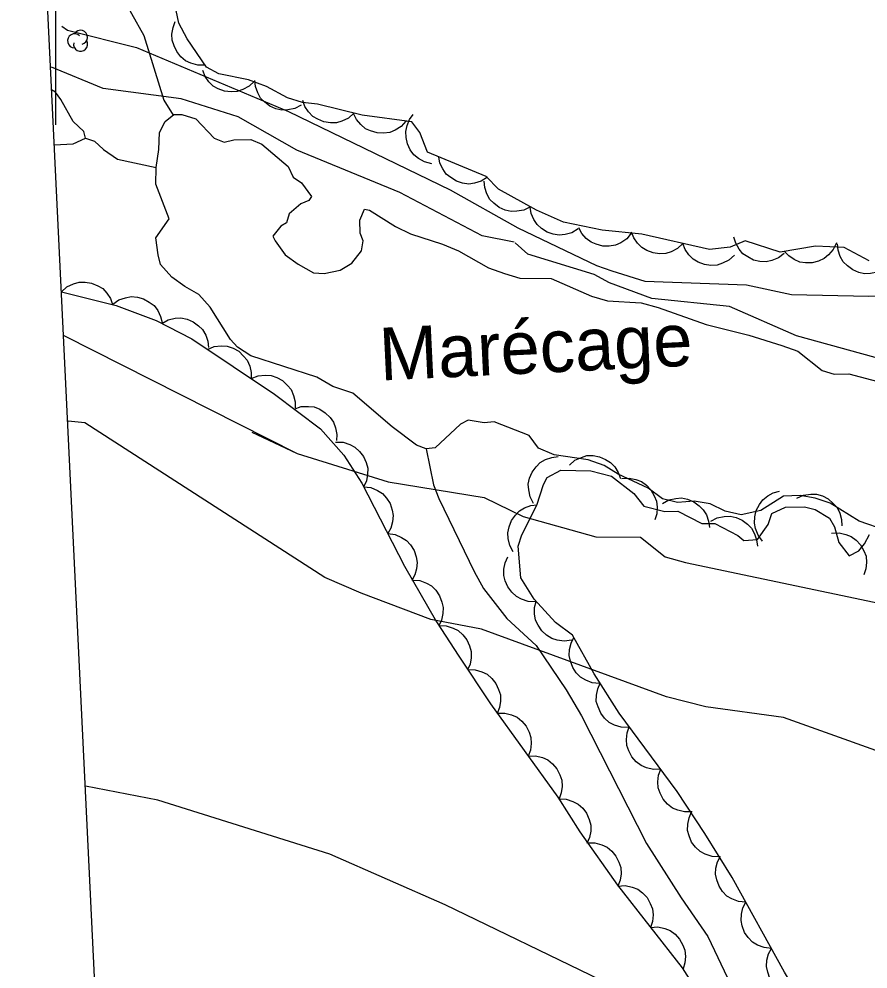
# Model space of a CAD drawing. Extents: x 336540 to 340074, y 5572036 to 5573747.
# Drawn here: x 336597.9 to 336646.2, y 5572741.9 to 5572796 of the extents above; entities that cross this region are included whole.
import ezdxf

# ---------------------------------------------------------------- set-up
doc = ezdxf.new("R2010")
doc.units = 0
for name, color, linetype in [('Niveau 1', 7, 'Continuous'), ('Niveau 2', 7, 'Continuous'), ('Niveau 22', 7, 'Continuous'), ('Niveau 4', 7, 'Continuous'), ('Niveau 44', 7, 'Continuous'), ('Niveau 60', 7, 'Continuous'), ('Niveau 61', 7, 'Continuous'), ('Niveau 7', 7, 'Continuous')]:
    doc.layers.add(name, color=color, linetype=linetype)

msp = doc.modelspace()

# ---------------------------------------------------------------- linework, layer by layer
at = {"layer": 'Niveau 1'}
for points in [[(336600.34, 5572795.62), (336600.66, 5572795.39), (336604.6, 5572794.4), (336613.25, 5572790.76), (336622.45, 5572786.3), (336626.3, 5572784.14), (336630.79, 5572781.99), (336631.65, 5572781.69), (336633.54, 5572781.11), (336639.32, 5572780.9), (336641.89, 5572780.34), (336646.29, 5572780.25), (336648.3, 5572780.35), (336651.23, 5572779.48), (336653.66, 5572778.24), (336658.28, 5572777.28), (336662.07, 5572775.8), (336664.13, 5572775.55), (336672.25, 5572771.92), (336679.3, 5572769.73), (336684.19, 5572766.93), (336687.33, 5572764.88), (336690.78, 5572763.71), (336694.11, 5572761.52)], [(336694.19, 5572736.91), (336688.36, 5572738.48), (336686.83, 5572738.57), (336684.3, 5572738.44), (336677.45, 5572739.96), (336675.38, 5572740.7), (336671.36, 5572743.38), (336667.54, 5572745.21), (336661.06, 5572749.46), (336659.52, 5572749.88), (336657.09, 5572751.12), (336649.35, 5572753.43), (336641.42, 5572756.25), (336637, 5572756.86), (336634.77, 5572757.43), (336624.24, 5572761.29), (336621.34, 5572761.83), (336617.38, 5572763.33), (336615.32, 5572764.23), (336601.64, 5572773.03), (336600.7, 5572773.13)]]:
    msp.add_lwpolyline(points, dxfattribs=at)
at = {"layer": 'Niveau 2'}
for points in [[(336626.1, 5572783.32), (336624.27, 5572783.69), (336619.58, 5572786.16), (336613.72, 5572788.57), (336610.38, 5572790.45), (336607.13, 5572791.48), (336602.7, 5572792.08), (336599.75, 5572793.28)], [(336650.91, 5572775.57), (336642.16, 5572777.99), (336638.36, 5572779.66), (336633.93, 5572780.12), (336631.52, 5572781), (336630.65, 5572781.48), (336626.87, 5572782.63), (336626.16, 5572783.28)], [(336600.46, 5572778.01), (336613.74, 5572771.28)], [(336611.15, 5572772.5), (336613.74, 5572771.28), (336618.92, 5572769.68), (336624.38, 5572768.78), (336626.61, 5572767.71), (336630.74, 5572766.55), (336633.28, 5572766.52), (336634.69, 5572765.41), (336635.85, 5572765.08), (336648.04, 5572762.52)], [(336697.14, 5572722.65), (336685.2, 5572724.41), (336674.58, 5572724.03), (336672.01, 5572724.41), (336669.09, 5572725.27), (336659.53, 5572730.2), (336654.62, 5572733.52), (336651.93, 5572733.2), (336650.72, 5572733.49), (336649, 5572734.41), (336645.55, 5572735.43), (336642.79, 5572736.48), (336631.03, 5572741.3), (336622.17, 5572745.59), (336615.6, 5572748.48), (336605.8, 5572751.55), (336601.69, 5572752.34)]]:
    msp.add_lwpolyline(points, dxfattribs=at)
at = {"layer": 'Niveau 22'}
for points in [[(336599.22, 5572803.16), (336601.52, 5572800.75), (336602.67, 5572799.12), (336603.61, 5572797.61), (336605.01, 5572795.09), (336606.15, 5572791.4), (336606.67, 5572790.55)], [(336621.09, 5572771.55), (336621.5, 5572769.5), (336621.8, 5572768.73), (336623.81, 5572764.56), (336624.34, 5572763.61), (336625.68, 5572761.89), (336627.35, 5572760.36), (336629.05, 5572757.84), (336629.93, 5572756.35), (336633.62, 5572749.08), (336635.61, 5572745.98), (336637.13, 5572743.78), (336638.43, 5572741.03)]]:
    msp.add_lwpolyline(points, dxfattribs=at)
at = {"layer": 'Niveau 4'}
for points in [[(336599.91, 5572788.86), (336600.99, 5572788.93), (336601.68, 5572789.24), (336601.6, 5572789.62), (336600.99, 5572790.2), (336600.29, 5572791.45), (336599.97, 5572791.87), (336599.76, 5572791.99)], [(336601.68, 5572789.24), (336602.19, 5572789.08), (336602.71, 5572788.59), (336603.51, 5572788.04), (336605.72, 5572787.58)]]:
    msp.add_lwpolyline(points, dxfattribs=at)
at = {"layer": 'Niveau 44'}
for points in [[(336646.31, 5572782.26), (336644.88, 5572783.02), (336643.25, 5572783.09), (336641.23, 5572782.76), (336639.24, 5572783.4), (336638.4, 5572783.04), (336637.22, 5572782.9), (336633.37, 5572783.77), (336631.11, 5572784), (336628.9, 5572784.46), (336627.37, 5572785.15), (336625.2, 5572786.34), (336624.5, 5572787.06), (336621.15, 5572788.45), (336620.73, 5572789.57), (336620.26, 5572790.18), (336617.44, 5572790.56), (336614.89, 5572791.18), (336614.04, 5572791.27), (336613.19, 5572791.54), (336611.99, 5572792.18), (336610.97, 5572792.56), (336609.27, 5572792.91), (336608.58, 5572793.29), (336607.47, 5572794.9), (336607, 5572795.79), (336606.69, 5572797.25)], [(336608.5, 5572793.41), (336608.08, 5572793.4), (336607.69, 5572793.52), (336607.39, 5572793.65), (336607.12, 5572793.88), (336606.89, 5572794.17), (336606.73, 5572794.51), (336606.62, 5572794.82), (336606.61, 5572795.17), (336606.67, 5572795.54), (336606.8, 5572795.88)], [(336611.3, 5572792.49), (336611, 5572792.2), (336610.64, 5572792.01), (336610.33, 5572791.9), (336609.98, 5572791.88), (336609.61, 5572791.93), (336609.25, 5572792.06), (336608.96, 5572792.21), (336608.71, 5572792.46), (336608.5, 5572792.76), (336608.36, 5572793.1)], [(336613.97, 5572791.12), (336613.6, 5572790.93), (336613.2, 5572790.85), (336612.87, 5572790.83), (336612.53, 5572790.91), (336612.19, 5572791.06), (336611.89, 5572791.29), (336611.65, 5572791.52), (336611.49, 5572791.83), (336611.36, 5572792.18), (336611.33, 5572792.53)], [(336616.97, 5572790.67), (336616.66, 5572790.39), (336616.29, 5572790.22), (336615.98, 5572790.12), (336615.63, 5572790.11), (336615.26, 5572790.17), (336614.91, 5572790.32), (336614.63, 5572790.48), (336614.39, 5572790.74), (336614.18, 5572791.05), (336614.06, 5572791.38)], [(336619.93, 5572790.22), (336619.66, 5572789.91), (336619.31, 5572789.7), (336619.01, 5572789.57), (336618.66, 5572789.52), (336618.29, 5572789.54), (336617.92, 5572789.66), (336617.62, 5572789.78), (336617.36, 5572790.02), (336617.12, 5572790.3), (336616.96, 5572790.62)], [(336621.4, 5572787.79), (336620.99, 5572787.89), (336620.64, 5572788.09), (336620.38, 5572788.3), (336620.18, 5572788.58), (336620.02, 5572788.92), (336619.94, 5572789.29), (336619.92, 5572789.62), (336620, 5572789.96), (336620.14, 5572790.31), (336620.34, 5572790.6)], [(336624.57, 5572787.03), (336624.22, 5572786.8), (336623.83, 5572786.68), (336623.51, 5572786.63), (336623.16, 5572786.68), (336622.81, 5572786.79), (336622.48, 5572787), (336622.23, 5572787.2), (336622.03, 5572787.49), (336621.87, 5572787.83), (336621.8, 5572788.18)], [(336627.02, 5572785.34), (336626.65, 5572785.15), (336626.25, 5572785.08), (336625.92, 5572785.06), (336625.58, 5572785.15), (336625.24, 5572785.3), (336624.94, 5572785.54), (336624.7, 5572785.76), (336624.54, 5572786.08), (336624.42, 5572786.43), (336624.39, 5572786.79)], [(336629.74, 5572784.08), (336629.38, 5572783.86), (336628.99, 5572783.76), (336628.66, 5572783.72), (336628.32, 5572783.78), (336627.97, 5572783.9), (336627.65, 5572784.11), (336627.4, 5572784.32), (336627.21, 5572784.62), (336627.07, 5572784.96), (336627, 5572785.31)], [(336632.76, 5572783.83), (336632.5, 5572783.51), (336632.16, 5572783.29), (336631.86, 5572783.15), (336631.51, 5572783.09), (336631.14, 5572783.1), (336630.77, 5572783.2), (336630.47, 5572783.32), (336630.2, 5572783.54), (336629.95, 5572783.82), (336629.78, 5572784.14)], [(336635.7, 5572783.24), (336635.4, 5572782.96), (336635.03, 5572782.78), (336634.72, 5572782.67), (336634.37, 5572782.66), (336634, 5572782.71), (336633.65, 5572782.85), (336633.36, 5572783.01), (336633.12, 5572783.26), (336632.91, 5572783.57), (336632.78, 5572783.9)], [(336641.47, 5572782.68), (336641.14, 5572782.43), (336640.76, 5572782.28), (336640.44, 5572782.2), (336640.09, 5572782.22), (336639.73, 5572782.3), (336639.39, 5572782.48), (336639.12, 5572782.66), (336638.9, 5572782.93), (336638.71, 5572783.26), (336638.61, 5572783.6)], [(336638.63, 5572782.58), (336638.32, 5572782.3), (336637.96, 5572782.12), (336637.65, 5572782.01), (336637.3, 5572782), (336636.93, 5572782.05), (336636.57, 5572782.19), (336636.29, 5572782.35), (336636.04, 5572782.6), (336635.83, 5572782.91), (336635.7, 5572783.24)], [(336644.44, 5572783.28), (336644.26, 5572782.91), (336643.99, 5572782.6), (336643.74, 5572782.39), (336643.42, 5572782.24), (336643.06, 5572782.15), (336642.68, 5572782.15), (336642.36, 5572782.19), (336642.03, 5572782.33), (336641.73, 5572782.54), (336641.48, 5572782.8)], [(336647.15, 5572781.81), (336646.78, 5572781.62), (336646.38, 5572781.54), (336646.05, 5572781.52), (336645.71, 5572781.6), (336645.37, 5572781.74), (336645.07, 5572781.98), (336644.83, 5572782.2), (336644.66, 5572782.51), (336644.54, 5572782.86), (336644.5, 5572783.22)], [(336600.32, 5572780.5), (336600.63, 5572780.78), (336601, 5572780.95), (336601.32, 5572781.05), (336601.67, 5572781.05), (336602.03, 5572780.99), (336602.38, 5572780.84), (336602.67, 5572780.68), (336602.9, 5572780.42), (336603.11, 5572780.11), (336603.23, 5572779.77)], [(336600.32, 5572780.5), (336603.43, 5572779.72), (336605.71, 5572778.87), (336607.74, 5572777.82), (336612.44, 5572774.67), (336615.07, 5572772.7), (336616.4, 5572771.2), (336617.42, 5572769.6), (336619.85, 5572764.87), (336621.67, 5572761.71), (336622.94, 5572759.74), (336624.75, 5572757.04), (336628.58, 5572751.72), (336629.83, 5572749.74), (336631.97, 5572746.7), (336635.65, 5572742.01), (336636.8, 5572740.21)], [(336603.24, 5572779.79), (336603.58, 5572780.03), (336603.96, 5572780.16), (336604.29, 5572780.23), (336604.64, 5572780.19), (336604.99, 5572780.09), (336605.32, 5572779.9), (336605.59, 5572779.71), (336605.8, 5572779.43), (336605.96, 5572779.09), (336606.05, 5572778.74)], [(336606.03, 5572778.7), (336606.4, 5572778.9), (336606.8, 5572778.99), (336607.12, 5572779.01), (336607.47, 5572778.93), (336607.81, 5572778.79), (336608.12, 5572778.56), (336608.35, 5572778.34), (336608.53, 5572778.03), (336608.65, 5572777.68), (336608.69, 5572777.33)], [(336608.63, 5572777.22), (336609.02, 5572777.38), (336609.42, 5572777.42), (336609.75, 5572777.4), (336610.09, 5572777.29), (336610.41, 5572777.11), (336610.69, 5572776.84), (336610.9, 5572776.6), (336611.04, 5572776.27), (336611.12, 5572775.91), (336611.12, 5572775.55)], [(336611.12, 5572775.55), (336611.51, 5572775.71), (336611.92, 5572775.75), (336612.25, 5572775.73), (336612.58, 5572775.62), (336612.9, 5572775.44), (336613.18, 5572775.17), (336613.39, 5572774.93), (336613.53, 5572774.6), (336613.62, 5572774.24), (336613.62, 5572773.88)], [(336613.57, 5572773.82), (336613.97, 5572773.96), (336614.38, 5572773.97), (336614.7, 5572773.94), (336615.03, 5572773.81), (336615.34, 5572773.61), (336615.61, 5572773.34), (336615.81, 5572773.08), (336615.93, 5572772.75), (336615.99, 5572772.38), (336615.98, 5572772.02)], [(336615.93, 5572771.94), (336616.35, 5572771.93), (336616.73, 5572771.8), (336617.03, 5572771.65), (336617.29, 5572771.41), (336617.51, 5572771.12), (336617.66, 5572770.77), (336617.76, 5572770.45), (336617.75, 5572770.1), (336617.69, 5572769.74), (336617.54, 5572769.41)], [(336629.24, 5572770.63), (336629.55, 5572770.9), (336629.92, 5572771.07), (336630.24, 5572771.17), (336630.59, 5572771.17), (336630.95, 5572771.1), (336631.3, 5572770.95), (336631.58, 5572770.78), (336631.82, 5572770.52), (336632.02, 5572770.21), (336632.14, 5572769.87)], [(336627.19, 5572768.45), (336627, 5572768.82), (336626.92, 5572769.22), (336626.89, 5572769.55), (336626.97, 5572769.89), (336627.12, 5572770.23), (336627.35, 5572770.53), (336627.57, 5572770.77), (336627.88, 5572770.94), (336628.23, 5572771.07), (336628.59, 5572771.11)], [(336630.65, 5572758.75), (336629.42, 5572760.95), (336628.45, 5572761.66), (336627.23, 5572762.99), (336626.47, 5572764.21), (336626.32, 5572766.02), (336626.53, 5572766.65), (336627.39, 5572768.35), (336627.76, 5572769.53), (336627.97, 5572769.93), (336628.75, 5572770.34), (336630.45, 5572770.31), (336631.64, 5572770), (336632.9, 5572769.01), (336633.48, 5572768.29), (336634.67, 5572767.98), (336635.41, 5572768), (336636.78, 5572767.3), (336637.51, 5572767.31), (336638.82, 5572766.61), (336639.17, 5572766.34), (336639.95, 5572766.4), (336640.56, 5572767.25), (336640.77, 5572767.87), (336641.55, 5572768.23), (336642.62, 5572768.25), (336643.24, 5572768.1), (336644.04, 5572767.61), (336644.34, 5572767.11), (336644.58, 5572766.22), (336645.17, 5572765.46), (336645.72, 5572765.75), (336646.05, 5572766.15), (336646.32, 5572766.67)], [(336632.22, 5572769.86), (336632.64, 5572769.89), (336633.03, 5572769.8), (336633.34, 5572769.69), (336633.63, 5572769.48), (336633.88, 5572769.22), (336634.07, 5572768.88), (336634.2, 5572768.58), (336634.23, 5572768.23), (336634.21, 5572767.86), (336634.1, 5572767.52)], [(336617.52, 5572769.4), (336617.94, 5572769.35), (336618.31, 5572769.18), (336618.59, 5572769.01), (336618.83, 5572768.75), (336619.03, 5572768.44), (336619.14, 5572768.07), (336619.21, 5572767.75), (336619.17, 5572767.4), (336619.07, 5572767.04), (336618.9, 5572766.73)], [(336640.24, 5572766.3), (336639.99, 5572766.63), (336639.84, 5572767.01), (336639.77, 5572767.33), (336639.8, 5572767.69), (336639.88, 5572768.04), (336640.07, 5572768.38), (336640.25, 5572768.65), (336640.53, 5572768.87), (336640.85, 5572769.04), (336641.2, 5572769.14)], [(336634.54, 5572768.45), (336634.9, 5572768.65), (336635.3, 5572768.73), (336635.63, 5572768.76), (336635.97, 5572768.68), (336636.32, 5572768.54), (336636.62, 5572768.31), (336636.86, 5572768.09), (336637.04, 5572767.79), (336637.16, 5572767.44), (336637.21, 5572767.08)], [(336642.19, 5572768.74), (336642.57, 5572768.91), (336642.98, 5572768.97), (336643.31, 5572768.97), (336643.64, 5572768.87), (336643.98, 5572768.7), (336644.26, 5572768.45), (336644.49, 5572768.21), (336644.64, 5572767.89), (336644.74, 5572767.53), (336644.75, 5572767.17)], [(336626.04, 5572765.69), (336625.84, 5572766.05), (336625.75, 5572766.45), (336625.73, 5572766.78), (336625.8, 5572767.12), (336625.94, 5572767.47), (336626.17, 5572767.77), (336626.39, 5572768.02), (336626.69, 5572768.19), (336627.04, 5572768.32), (336627.4, 5572768.36)], [(336637.29, 5572767.43), (336637.66, 5572767.62), (336638.06, 5572767.7), (336638.39, 5572767.72), (336638.73, 5572767.64), (336639.07, 5572767.49), (336639.37, 5572767.26), (336639.61, 5572767.03), (336639.78, 5572766.72), (336639.9, 5572766.37), (336639.94, 5572766.01)], [(336618.9, 5572766.73), (336619.31, 5572766.68), (336619.68, 5572766.51), (336619.96, 5572766.34), (336620.2, 5572766.08), (336620.4, 5572765.77), (336620.51, 5572765.4), (336620.58, 5572765.08), (336620.54, 5572764.73), (336620.44, 5572764.38), (336620.27, 5572764.06)], [(336644.17, 5572766.75), (336644.59, 5572766.78), (336644.98, 5572766.68), (336645.29, 5572766.57), (336645.57, 5572766.35), (336645.82, 5572766.08), (336646, 5572765.74), (336646.13, 5572765.44), (336646.15, 5572765.09), (336646.12, 5572764.72), (336646.01, 5572764.38)], [(336627.32, 5572762.85), (336626.9, 5572762.87), (336626.51, 5572763), (336626.22, 5572763.15), (336625.96, 5572763.39), (336625.74, 5572763.69), (336625.59, 5572764.04), (336625.5, 5572764.35), (336625.51, 5572764.71), (336625.58, 5572765.07), (336625.73, 5572765.4)], [(336620.3, 5572764.08), (336620.72, 5572764.05), (336621.1, 5572763.9), (336621.39, 5572763.75), (336621.64, 5572763.5), (336621.85, 5572763.19), (336621.98, 5572762.83), (336622.06, 5572762.52), (336622.04, 5572762.17), (336621.96, 5572761.8), (336621.8, 5572761.48)], [(336629.37, 5572760.66), (336628.95, 5572760.6), (336628.55, 5572760.66), (336628.23, 5572760.75), (336627.94, 5572760.94), (336627.67, 5572761.19), (336627.46, 5572761.51), (336627.31, 5572761.8), (336627.25, 5572762.15), (336627.26, 5572762.52), (336627.34, 5572762.87)], [(336621.81, 5572761.49), (336622.23, 5572761.48), (336622.62, 5572761.35), (336622.91, 5572761.21), (336623.17, 5572760.97), (336623.4, 5572760.68), (336623.55, 5572760.33), (336623.65, 5572760.01), (336623.64, 5572759.66), (336623.58, 5572759.3), (336623.44, 5572758.97)], [(336630.96, 5572758.2), (336630.54, 5572758.23), (336630.17, 5572758.38), (336629.88, 5572758.55), (336629.63, 5572758.8), (336629.43, 5572759.1), (336629.3, 5572759.47), (336629.22, 5572759.78), (336629.25, 5572760.13), (336629.33, 5572760.49), (336629.5, 5572760.82)], [(336623.45, 5572758.98), (336623.87, 5572758.97), (336624.26, 5572758.85), (336624.56, 5572758.72), (336624.82, 5572758.48), (336625.05, 5572758.2), (336625.21, 5572757.85), (336625.31, 5572757.54), (336625.32, 5572757.18), (336625.26, 5572756.82), (336625.12, 5572756.48)], [(336675.72, 5572687.3), (336670.57, 5572695.3), (336667.1, 5572701.04), (336665.5, 5572704.03), (336664.03, 5572706.99), (336662.49, 5572709.78), (336660.76, 5572712.48), (336656.84, 5572717.95), (336655.07, 5572720.56), (336648.64, 5572731.15), (336643.11, 5572739.06), (336641.48, 5572741.76), (336638.51, 5572747.14), (336636.95, 5572749.66), (336635.37, 5572752.04), (336632.08, 5572756.5), (336630.65, 5572758.75)], [(336632.6, 5572755.68), (336632.18, 5572755.7), (336631.8, 5572755.82), (336631.5, 5572755.97), (336631.24, 5572756.21), (336631.02, 5572756.5), (336630.87, 5572756.86), (336630.77, 5572757.17), (336630.78, 5572757.52), (336630.85, 5572757.89), (336630.99, 5572758.22)], [(336625.14, 5572756.5), (336625.56, 5572756.51), (336625.95, 5572756.4), (336626.26, 5572756.27), (336626.53, 5572756.05), (336626.77, 5572755.77), (336626.94, 5572755.43), (336627.05, 5572755.12), (336627.06, 5572754.77), (336627.02, 5572754.4), (336626.89, 5572754.06)], [(336634.44, 5572753.31), (336634.02, 5572753.29), (336633.62, 5572753.39), (336633.32, 5572753.52), (336633.04, 5572753.74), (336632.8, 5572754.01), (336632.63, 5572754.36), (336632.51, 5572754.66), (336632.49, 5572755.01), (336632.53, 5572755.38), (336632.65, 5572755.72)], [(336626.89, 5572754.06), (336627.31, 5572754.07), (336627.7, 5572753.97), (336628.01, 5572753.84), (336628.28, 5572753.62), (336628.52, 5572753.34), (336628.69, 5572752.99), (336628.8, 5572752.68), (336628.82, 5572752.33), (336628.77, 5572751.96), (336628.65, 5572751.63)], [(336636.22, 5572750.89), (336635.8, 5572750.88), (336635.41, 5572750.98), (336635.1, 5572751.1), (336634.83, 5572751.32), (336634.58, 5572751.6), (336634.41, 5572751.94), (336634.29, 5572752.25), (336634.27, 5572752.6), (336634.32, 5572752.97), (336634.44, 5572753.31)], [(336628.64, 5572751.62), (336629.06, 5572751.61), (336629.44, 5572751.48), (336629.74, 5572751.33), (336630, 5572751.09), (336630.22, 5572750.8), (336630.37, 5572750.45), (336630.46, 5572750.13), (336630.45, 5572749.78), (336630.39, 5572749.42), (336630.24, 5572749.09)], [(336637.78, 5572748.33), (336637.36, 5572748.34), (336636.97, 5572748.48), (336636.68, 5572748.63), (336636.42, 5572748.87), (336636.2, 5572749.16), (336636.06, 5572749.52), (336635.97, 5572749.83), (336635.98, 5572750.18), (336636.05, 5572750.55), (336636.2, 5572750.88)], [(336630.28, 5572749.11), (336630.69, 5572749.12), (336631.08, 5572749), (336631.39, 5572748.87), (336631.66, 5572748.65), (336631.89, 5572748.36), (336632.06, 5572748.02), (336632.17, 5572747.71), (336632.18, 5572747.36), (336632.13, 5572746.99), (336632, 5572746.65)], [(336639.29, 5572745.74), (336638.87, 5572745.77), (336638.49, 5572745.93), (336638.21, 5572746.09), (336637.96, 5572746.34), (336637.76, 5572746.65), (336637.63, 5572747.01), (336637.56, 5572747.33), (336637.58, 5572747.68), (336637.67, 5572748.04), (336637.84, 5572748.36)], [(336632, 5572746.66), (336632.42, 5572746.69), (336632.82, 5572746.6), (336633.13, 5572746.48), (336633.41, 5572746.27), (336633.66, 5572746), (336633.84, 5572745.66), (336633.97, 5572745.36), (336634, 5572745.01), (336633.97, 5572744.64), (336633.86, 5572744.3)], [(336640.74, 5572743.11), (336640.32, 5572743.15), (336639.94, 5572743.3), (336639.66, 5572743.46), (336639.41, 5572743.72), (336639.21, 5572744.02), (336639.08, 5572744.39), (336639.01, 5572744.7), (336639.03, 5572745.05), (336639.12, 5572745.41), (336639.29, 5572745.74)], [(336633.86, 5572744.3), (336634.27, 5572744.33), (336634.67, 5572744.24), (336634.98, 5572744.12), (336635.26, 5572743.91), (336635.51, 5572743.64), (336635.69, 5572743.3), (336635.82, 5572743), (336635.85, 5572742.65), (336635.82, 5572742.28), (336635.71, 5572741.94)], [(336642.19, 5572740.48), (336641.77, 5572740.52), (336641.39, 5572740.67), (336641.11, 5572740.84), (336640.86, 5572741.09), (336640.66, 5572741.4), (336640.53, 5572741.76), (336640.46, 5572742.08), (336640.48, 5572742.43), (336640.57, 5572742.79), (336640.74, 5572743.11)]]:
    msp.add_lwpolyline(points, dxfattribs=at)
for centre, start, end in [((336601.063, 5572794.789), 44.1154, 269.804), ((336601.407, 5572794.989), 282.2692, 149.7263), ((336601.407, 5572794.589), 166.9369, 29.6212)]:
    msp.add_arc(centre, 0.4, start, end, dxfattribs=at)
at = {"layer": 'Niveau 60'}
msp.add_lwpolyline([(339458.94, 5573698.73), (339531.5, 5572199.65), (336635.22, 5572059.46), (336562.66, 5573558.54), (339458.94, 5573698.73)], dxfattribs=at)
at = {"layer": 'Niveau 61'}
msp.add_lwpolyline([(336600, 5572790), (336600, 5572810)], dxfattribs=at)
at = {"layer": 'Niveau 7'}
for points in [[(336605.72, 5572787.58), (336605.87, 5572788.6), (336605.9, 5572789.56), (336606.23, 5572790.19), (336606.72, 5572790.59), (336607.18, 5572790.6), (336607.97, 5572790.34), (336609.01, 5572789.24), (336609.58, 5572789.02), (336610.14, 5572789.15), (336611.1, 5572789.17), (336611.73, 5572788.9), (336613.23, 5572787.64), (336613.52, 5572787.02), (336613.98, 5572786.7), (336614.56, 5572785.92), (336614.4, 5572785.69), (336613.95, 5572785.51), (336613.29, 5572784.93), (336613.13, 5572784.42), (336612.8, 5572784.24), (336612.36, 5572783.67), (336612.48, 5572783.39), (336613.06, 5572782.61), (336613.8, 5572782.07), (336614.66, 5572781.58), (336615.28, 5572781.53), (336616.18, 5572781.72), (336616.85, 5572782.13), (336617.4, 5572782.82), (336617.5, 5572783.39), (336617.32, 5572783.84), (336617.3, 5572784.57), (336617.57, 5572785.2), (336617.85, 5572785.15), (336619.34, 5572784.22), (336620.2, 5572783.79), (336622.02, 5572783.21), (336622.93, 5572782.83), (336624.64, 5572781.86), (336625.55, 5572781.54), (336626.41, 5572781.28), (336628.21, 5572781.26), (336630.49, 5572780.24), (336631.4, 5572779.98), (336633.32, 5572779.86), (336634.29, 5572779.6), (336637.02, 5572778.64), (336639.46, 5572778.02), (336641.34, 5572777.44), (336642.25, 5572777.12), (336643.63, 5572776.02), (336644.31, 5572775.81), (336645.15, 5572775.83), (336647.08, 5572775.31)], [(336641.42, 5572768.86), (336640.14, 5572768.04), (336639.02, 5572767.79), (336638.11, 5572768), (336637.25, 5572768.43), (336636.35, 5572768.58), (336635.39, 5572768.5), (336634.54, 5572768.71), (336633.73, 5572769.31), (336632.02, 5572770.12), (336631.22, 5572770.61), (336630.31, 5572770.92), (336628.38, 5572771.22), (336627.47, 5572771.59), (336626.95, 5572772.31), (336624.95, 5572773.1), (336624.39, 5572773.03), (336623.48, 5572773.18), (336623.04, 5572772.95), (336621.6, 5572771.62), (336621.09, 5572771.55), (336620.53, 5572771.76), (336619.15, 5572772.8), (336616.9, 5572774.73), (336615.76, 5572775.1), (336614.85, 5572775.64), (336611.1, 5572776.85), (336610.35, 5572777.34), (336609.95, 5572777.78), (336608.78, 5572779.63), (336608.14, 5572780.35), (336607.34, 5572780.79), (336606.6, 5572781.33), (336605.96, 5572782.05), (336605.83, 5572782.61), (336605.7, 5572783.57), (336606.46, 5572784.66), (336605.69, 5572786.62), (336605.72, 5572787.58)], [(336647.28, 5572766.91), (336645.74, 5572767.44), (336644.08, 5572768.47), (336643.23, 5572768.74), (336642.38, 5572768.89), (336641.42, 5572768.86)]]:
    msp.add_lwpolyline(points, dxfattribs=at)

# ---------------------------------------------------------------- texts
msp.add_text('Marécage', height=3, rotation=2.7712, dxfattribs=at).set_placement((336618.48, 5572775.44))

doc.saveas('drawing.dxf')
